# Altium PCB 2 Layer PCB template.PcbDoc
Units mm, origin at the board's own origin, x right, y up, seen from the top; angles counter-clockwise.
Board outline 100 x 100 mm, 2 copper layers (Top, Bottom), stack 1.67 mm thick; 2 components, 0 nets, 4 pads, 0 vias.
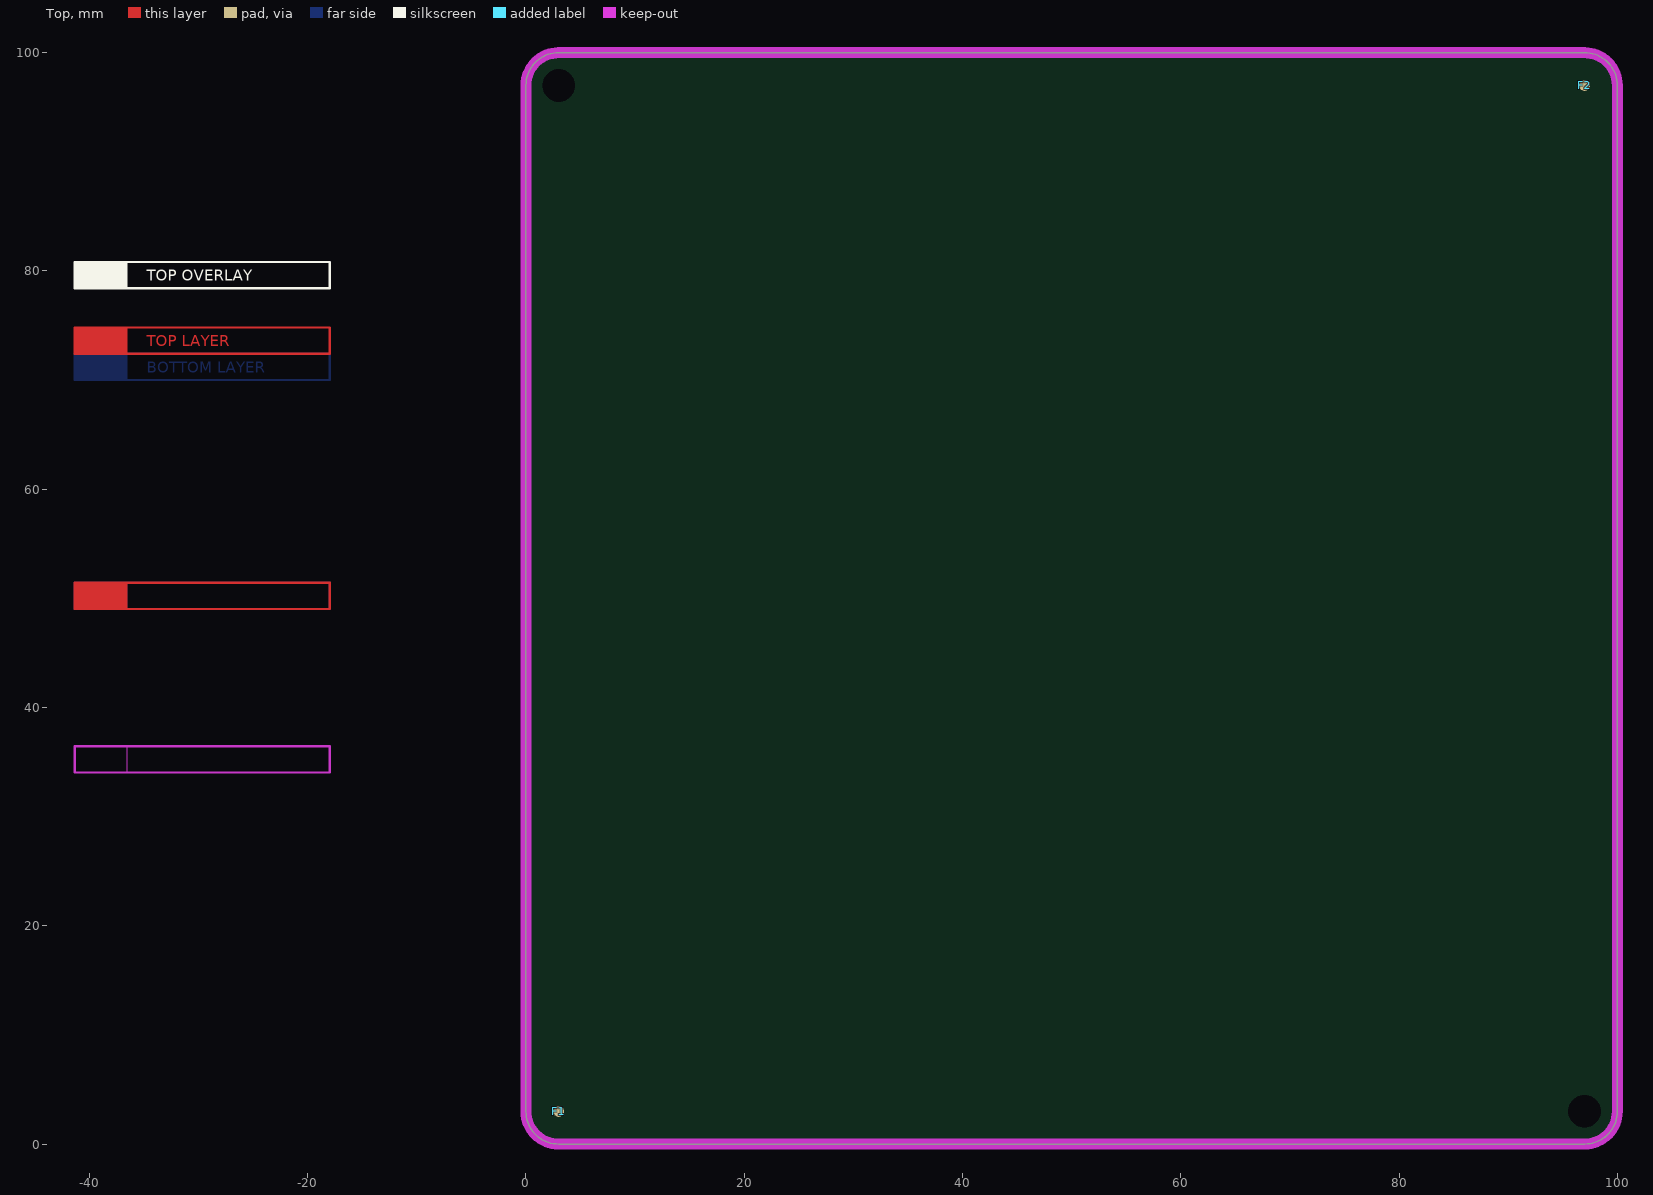
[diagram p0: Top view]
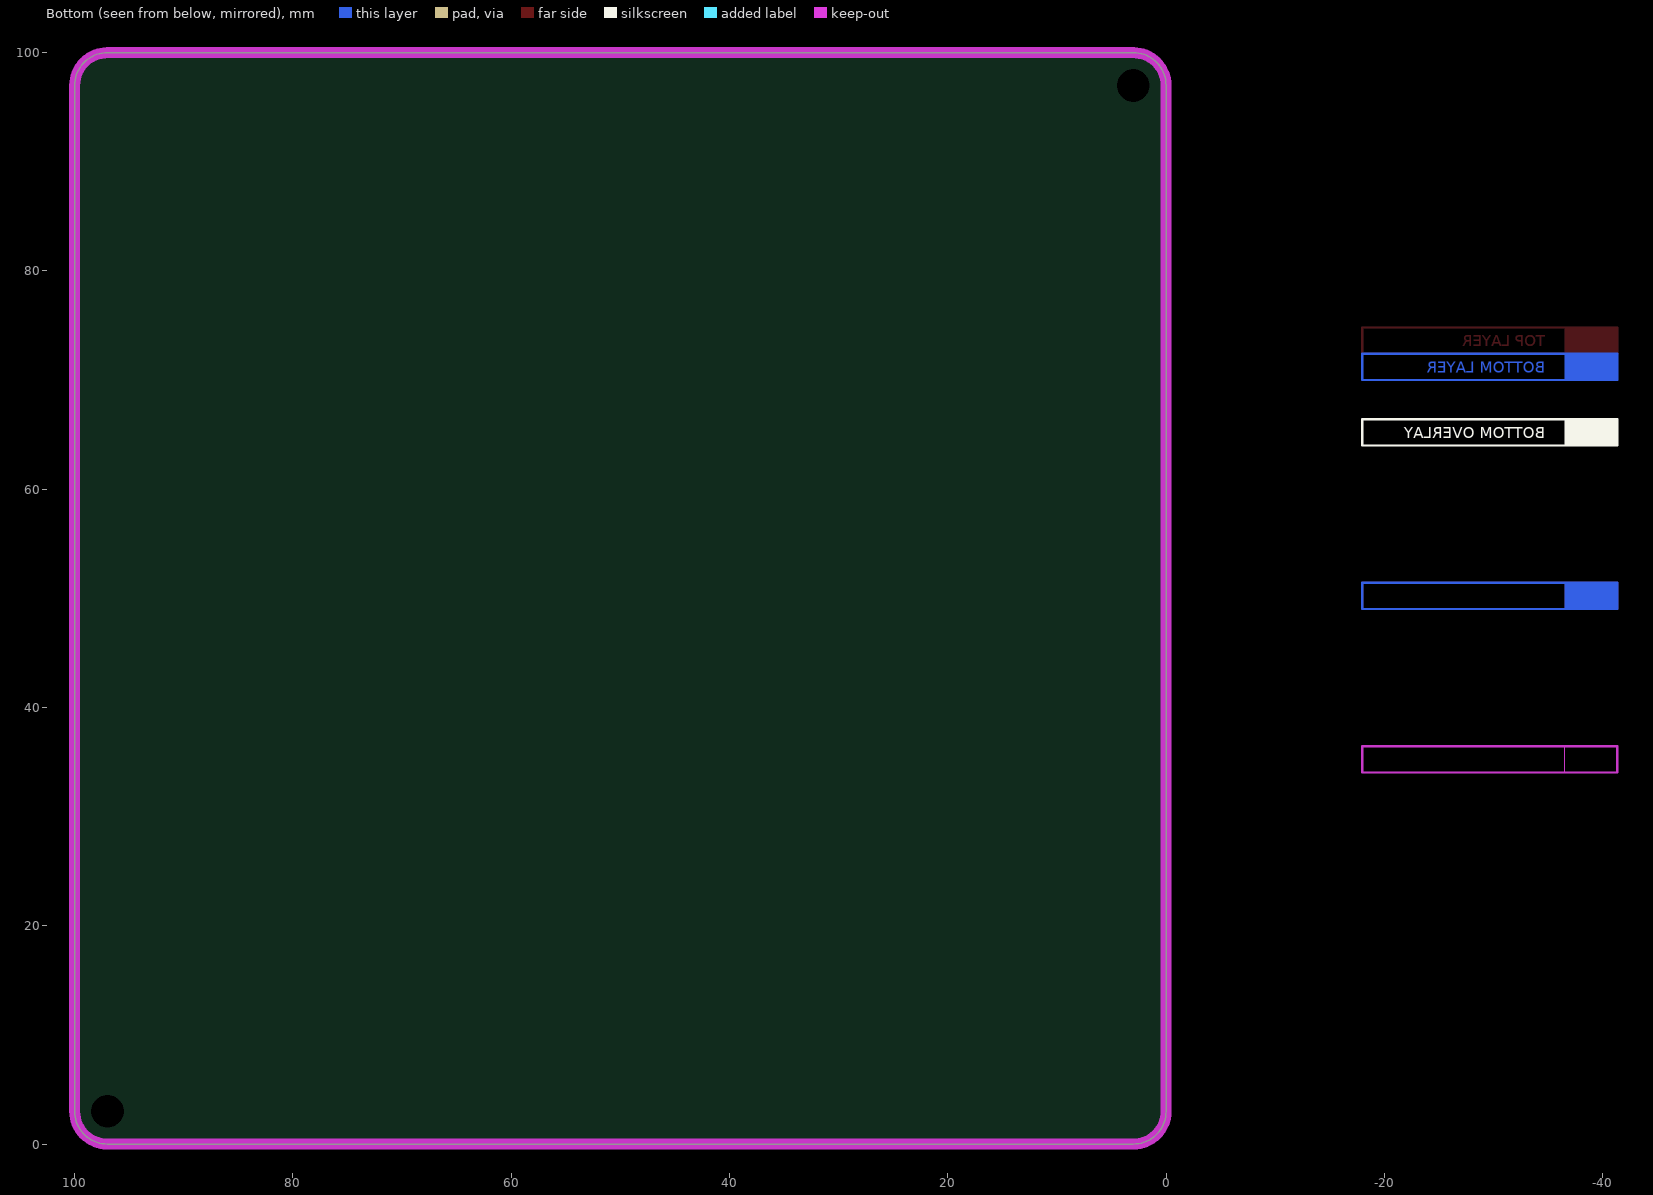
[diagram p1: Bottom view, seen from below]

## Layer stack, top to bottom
Top: signal copper 0.035
Dielectric: core 1.6, FR-4, Dk 4.8
Bottom: signal copper 0.035

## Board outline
0,3 0,97 cw(c3,97) 3,100 97,100 cw(c97,97) 100,97 100,3 cw(c97,3) 97,0 3,0 cw(c3,3)

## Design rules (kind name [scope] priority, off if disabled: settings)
AssemblyTestPointUsage [All] p1 off:
AssemblyTestpoint [All] p1 off: testpointundercomponent=TRUE minsize=1.016 maxsize=2.54 preferedsize=1.524 minholesize=0 maxholesize=1.016 preferedholesize=0.813 testpointgrid=0.025 usegrid=TRUE gridtolerance=0 allowsidetop=TRUE allowsidebottom=TRUE
Clearance ClearanceViaPad [IsVia vs IsPad] p1: gap=0.1
Clearance ClearanceGNDpolygons [InPolygonClass('GNDpolygons')] p2: gap=0.3
Clearance ClearanceTechnology [All] p3: gap=0.2
FabricationTestPointUsage [All] p1 off: valid=0 allowmultiple=FALSE
FabricationTestpoint [All] p1 off: side=3 testpointundercomponent=TRUE minsize=1.016 maxsize=2.54 preferedsize=1.524 minholesize=0 maxholesize=1.016 preferedholesize=0.813 testpointgrid=0.025 allowsidetop=TRUE allowsidebottom=TRUE usegrid=TRUE gridtolerance=0
HoleSize [All] p1: absolutevalues=TRUE maxlimit=6.3 minlimit=0.3 maxpercent=80.000 minpercent=20.000
HoleToHoleClearance [All] p1: gap=0.3 allowstackedmicrovias=TRUE
MinimumAnnularRing [All] p1: minimumring=0.2
MinimumSolderMaskSliver [All] p1: minsoldermaskwidth=0.1
PlaneClearance [All] p1: clearance=0.25
PolygonConnect PolygonConnectVia [IsVia] p1: connectstyle=Direct reliefconductorwidth=0.4 reliefentries=4 polygonreliefangle="90 Angle" airgapwidth=0.254
PolygonConnect PolygonConnectBigPads [(ObjectKind = 'Pad') And ((AsMM(PadXSize_AllLayers) > 2) Or (AsMM(PadYSize_AllLayers) > 2))] p2: connectstyle=Direct reliefconductorwidth=0.4 reliefentries=4 polygonreliefangle="90 Angle" airgapwidth=0.254
PolygonConnect PolygonConnectGeneral [All] p3: connectstyle=Relief reliefconductorwidth=0.3 reliefentries=4 polygonreliefangle="90 Angle" airgapwidth=0.2
RoutingVias [All] p1: holewidth=0.6 width=1.2 viastyle="Through Hole" minholewidth=0.3 minwidth=0.7 maxholewidth=0.9 maxwidth=1.4
SilkToSilkClearance [All] p1: silktosilkclearance=0.15
SilkToSolderMaskClearance SilkscreenOverComponentPads [IsPad] p1: minsilkscreentomaskgap=0.1 clearancetoexposedcopper=FALSE
SolderMaskExpansion [All] p1: expansion=0.1
Width WidthTechnology [All] p1: maxlimit=3 minlimit=0.16 preferedwidth=0.6
18 further rules are at their usual default settings.

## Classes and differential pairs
channel class "Column driver": "U_Column driver 1" "U_Column driver 2" "U_Column driver 3" "U_Column driver 4"
channel class "Row driver": "U_Row driver 1" "U_Row driver 2" "U_Row driver 3" "U_Row driver 4" "U_Row driver 5" "U_Row driver 6" "U_Row driver 7" "U_Row driver 8"

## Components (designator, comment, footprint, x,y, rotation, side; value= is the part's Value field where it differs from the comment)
F1 "Fiducial" FIDUCIAL 3,3 r90 top locked
F2 "Fiducial" FIDUCIAL 97,97 r90 top locked

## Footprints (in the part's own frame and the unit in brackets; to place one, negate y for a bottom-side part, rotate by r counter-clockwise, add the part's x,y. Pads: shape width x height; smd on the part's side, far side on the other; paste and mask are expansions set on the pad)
FIDUCIAL [mm] "Fiducial"
  round 1 smd paste-1 mask+0.5: ""(0,0)
  body extent -0.49,-0.5 0.5,0.5, height 0.5

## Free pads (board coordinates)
  round 1 hole 3: 0(3,97) 0(97,3)

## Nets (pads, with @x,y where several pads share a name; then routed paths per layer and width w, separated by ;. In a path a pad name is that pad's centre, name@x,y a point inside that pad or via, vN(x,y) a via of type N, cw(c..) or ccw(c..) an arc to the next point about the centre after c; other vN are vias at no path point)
pads on no net: F1. F2.
copper on no net: | length 103.1
  Top w0.2: -41.342,72.414 -41.342,74.827 -17.974,74.827 -17.974,72.414 -41.342,72.414
  Bottom w0.2: -41.342,70.001 -41.342,72.414 -17.974,72.414 -17.974,70.001 -41.342,70.001

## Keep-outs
Keep-Out Layer:
  rectangle: -41.342,34.035 -36.516,36.448
  lines w0.2: -41.342,34.035 -41.342,36.448 -17.974,36.448 -17.974,34.035 -41.342,34.035
  lines w1: 3,100 ccw(c3,97) 0,97 0,3 ccw(c3,3) 3,0 97,0 ccw(c97,3) 100,3 ; 3,100 3,100 ; 3,100 97,100 ; 97,100 cw(c97,97) 100,97 ; 97,100 97,100 ; 100,3 100,97 ; 100,3 100,3 ; 100,97 100,97
  text "ROUTING KEEPOUT LAYER" at -34.738,34.721 h0.89

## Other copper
Top:
  rectangle: -41.342,72.414 -36.516,74.827
  text "TOP LAYER" at -34.738,73.1 h1.02
Bottom:
  rectangle: -41.342,70.001 -36.516,72.414
  text "BOTTOM LAYER" at -34.738,70.687 h1.02
Multi-Layer:
  rectangle: -41.342,49.021 -36.516,51.434
  lines w0.2: -41.342,49.021 -41.342,51.434 -17.974,51.434 -17.974,49.021 -41.342,49.021
  text "MULTILAYER" at -34.738,49.707 h1.02

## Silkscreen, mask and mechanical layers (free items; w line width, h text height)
Top Overlay:
  rectangle: -41.342,78.409 -36.516,80.822
  lines w0.2: -41.342,78.409 -17.974,78.409 -17.974,80.822 -41.342,80.822 -41.342,78.409
  text "TOP OVERLAY" at -34.738,79.094 h1.02
Bottom Overlay:
  rectangle: -41.342,64.007 -36.516,66.42
  lines w0.2: -41.342,64.007 -17.974,64.007 -17.974,66.42 -41.342,66.42 -41.342,64.007
  text "BOTTOM OVERLAY" at -34.738,64.693 h1.02
Top Paste:
  rectangle: -41.342,81.406 -36.516,83.819
  lines w0.2: -41.342,81.406 -41.342,83.819 -17.974,83.819 -17.974,81.406 -41.342,81.406
  text "TOP PASTE" at -34.738,82.092 h1.02
Bottom Paste:
  rectangle: -41.342,61.01 -36.516,63.423
  lines w0.2: -41.342,61.01 -41.342,63.423 -17.974,63.423 -17.974,61.01 -41.342,61.01
  text "BOTTOM PASTE" at -34.738,61.695 h1.02
Top Solder:
  rectangle: -41.342,75.411 -36.516,77.824
  lines w0.2: -41.342,75.411 -17.974,75.411 -17.974,77.824 -41.342,77.824 -41.342,75.411
  text "TOP SOLDER MASK" at -34.738,76.097 h1.02
Bottom Solder:
  rectangle: -41.342,67.004 -36.516,69.417
  lines w0.2: -41.342,67.004 -41.342,69.417 -17.974,69.417 -17.974,67.004 -41.342,67.004
  text "BOTTOM SOLDER MASK" at -34.738,67.69 h1.02
Drill Guide:
  rectangle: -41.342,58.012 -36.516,60.425
  lines w0.2: -41.342,58.012 -17.974,58.012 -17.974,60.425 -41.342,60.425 -41.342,58.012
  text "DRILL GUIDE (SLOTS)" at -34.738,58.698 h1.02
Outline:
  rectangle: -41.342,52.018 -36.516,54.431
  lines w0.1: 0,3 ccw(c3,3) 3,0 97,0 ccw(c97,3) 100,3 100,97 ccw(c97,97) 97,100 3,100 ccw(c3,97) 0,97 0,3
  lines w0.2: -41.342,52.018 -17.974,52.018 -17.974,54.431 -41.342,54.431 -41.342,52.018
  lines w0.25: 119.824,-28.075 248.576,-28.075 ; 119.824,-23.725 248.576,-23.725 ; 118.3,-48 ccw(c119.7,-48) 119.7,-49.4 248.7,-49.4 ccw(c248.7,-48) 250.1,-48 250.1,-19 ccw(c248.7,-19) 248.7,-17.6 119.7,-17.6 ccw(c119.7,-19) 118.3,-19 118.3,-48
  lines w0.254: -43.882,117.702 69,117.702 69,112 ; -43.882,122.827 69,122.827 69,117.136 ; -39.056,86.105 -19.498,86.105 ; 33,112 33,117.702 ; 69,122.825 94.975,122.825 ; -43.882,31.825 -43.882,91.693 -15.18,91.693 -15.18,31.825 -43.882,31.825 ; -43.882,112 95,112 95,130.05 -43.882,130.05 -43.882,112
  text ".GlobalProjectName" at -32.125,124.975 h3
  text "Project:" at -42.406,124.816 h1.2
  text ".GlobalProjectTeam" at -34.65,119.3 h2.03
  text ".GlobalProjectLink" at 35.15,119.3 h2.03
  text "Team:" at -42.406,119.225 h1.2
  text "More info:" at 25.35,119.225 h1.2
  text ".GlobalProjectRevision" at 75,114 h7
  text ".Pcb_File_Name_No_Path" at -28,113.934 h2.03
  text "PCB file name:" at -42.406,113.907 h1.2
  text ".GlobalRevisionDate" at 48.119,113.507 h2.03
  text "Rev:" at 71,113.507 h1.2
  text "Revision date:" at 34.944,113.407 h1.2
  text "LAYER USAGE" at -39.056,86.816 h2.03
  text "Fusion service size limits" at 131,76.8 h5
  text "5cm X 5cm" at 134,71.802 h5
  text "5cm X 10cm" at 134,68.024 h5
  text "5cm X 15cm" at 134,64.246 h5
  text "5cm X 20cm" at 134,60.468 h5
  text "10cm X 10cm" at 134,56.69 h5
  text "10cm X 15cm" at 134,52.912 h5
  text "BOARD OUTLINE" at -34.738,52.704 h1.02
  text "10cm X 20cm" at 134,49.134 h5
  text "15cm X 15cm" at 134,45.356 h5
  text "15cm X 20cm" at 134,41.578 h5
  text "20cm X 20cm" at 134,37.8 h5
  text "Layer Stack Up Detail for: 2 Layer Seed Fusion template" at 119.824,-22.178 h2.05
  text "Layer" at 119.824,-25.35 h1
  text "Gerber" at 147.375,-25.35 h1
  text "Copper" at 161.317,-25.35 h1
  text "Dielectric" at 176.892,-25.35 h1
  text "Dielectric" at 193.166,-25.35 h1
  text "Dielectric" at 213.72,-25.35 h1
  text "Dielectric" at 229.994,-25.35 h1
  text "Name" at 119.824,-27.35 h1
  text "Document" at 147.375,-27.35 h1
  text "Thickness" at 161.317,-27.35 h1
  text "Height" at 176.892,-27.35 h1
  text "Material" at 193.166,-27.35 h1
  text "Constant" at 213.72,-27.35 h1
  text "Type" at 229.994,-27.35 h1
  text "Top Solder Mask" at 119.824,-31.222 h1.4
  text "(.GTS)" at 147.375,-31.222 h1.4
  text "0.0102mm" at 176.892,-31.222 h1.4
  text "Solder Resist" at 193.166,-31.222 h1.4
  text "3.50" at 213.72,-31.222 h1.4
  text "Top" at 119.824,-35.252 h1.4
  text "(.GTL)" at 147.375,-35.252 h1.4
  text "0.035mm" at 161.317,-35.252 h1.4
  text "1.6mm" at 176.892,-37.267 h1.4
  text "FR-4" at 193.166,-37.267 h1.4
  text "4.80" at 213.72,-37.267 h1.4
  text "Core" at 229.994,-37.267 h1.4
  text "Bottom" at 119.824,-39.282 h1.4
  text "(.GBL)" at 147.375,-39.282 h1.4
  text "0.035mm" at 161.317,-39.282 h1.4
  text "Bottom Solder Mask" at 119.824,-43.312 h1.4
  text "(.GBS)" at 147.375,-43.312 h1.4
  text "0.0102mm" at 176.892,-43.312 h1.4
  text "Solder Resist" at 193.166,-43.312 h1.4
  text "3.50" at 213.72,-43.312 h1.4
Dimensions:
  rectangle: -41.342,37.032 -36.516,39.445
  lines w0.2: -41.146,-10.834 -23.061,-10.834 ; -41.07,-2.782 -22.985,-2.782 ; -41.07,16.369 -22.985,16.369 ; -41.045,8.673 -22.96,8.673 ; -40.918,19.798 -22.833,19.798 ; -41.342,37.032 -17.974,37.032 -17.974,39.445 -41.342,39.445 -41.342,37.032
  lines w0.254: -42.064,-17.8 -42.064,23.583 -17.908,23.583 -17.908,-17.8 -42.064,-17.8
  text "DIMENSIONS" at -34.738,37.718 h1.02
  text "BUILD STATISTICS" at -40.816,20.586 h1.52
  text "GENERAL" at -41.019,16.877 h1.02
  text ".Net_Count" at -31.342,14.769 h1.02
  text "NETS" at -40.943,14.718 h0.89
  text ".Component_Count" at -31.342,12.686 h1.02
  text "COMPONENTS" at -40.918,12.661 h0.89
  text "PRIMITIVES" at -40.994,9.181 h1.02
  text ".Fill_Count" at -31.342,7.048 h1.02
  text "FILLS" at -40.918,7.022 h0.89
  text ".Track_Count" at -31.342,4.99 h1.02
  text "TRACKS" at -40.918,4.939 h0.89
  text ".String_Count" at -31.342,2.907 h1.02
  text "STRINGS" at -40.918,2.857 h0.89
  text ".Arc_Count" at -31.342,0.799 h1.02
  text "ARC'S" at -40.918,0.748 h0.89
  text "LANDS" at -41.019,-2.274 h1.02
  text ".Pad_Count" at -31.342,-4.408 h1.02
  text ".Pad_Count" at -31.342,-4.408 h1.02
  text "PADS" at -40.918,-4.459 h0.89
  text ".Via_Count" at -31.342,-6.491 h1.02
  text "VIA'S" at -40.892,-6.516 h0.89
  text "PRINT SCALE" at -41.095,-10.326 h1.02
  text ".Print_Scale" at -31.393,-12.485 h1.02
  text "SCALE" at -40.968,-12.51 h0.89
  text ".Print_Date" at -31.393,-14.542 h1.02
  text "PRINT DATE" at -40.943,-14.568 h0.89
  text ".Print_Time" at -31.367,-16.6 h1.02
  text "PRINT TIME" at -40.918,-16.625 h0.89
Assembly Top:
  rectangle: -41.342,46.024 -36.516,48.437
  lines w0.2: -41.342,46.024 -41.342,48.437 -17.974,48.437 -17.974,46.024 -41.342,46.024
  text "TOP ASSEMBLY" at -34.738,46.709 h1.02
Assembly Bot:
  rectangle: -41.342,43.026 -36.516,45.439
  lines w0.2: -41.342,43.026 -41.342,45.439 -17.974,45.439 -17.974,43.026 -41.342,43.026
  text "BOTTOM ASSEMBLY" at -34.738,43.712 h1.02
Drill Drawing:
  rectangle: -41.342,55.015 -36.516,57.428
  lines w0.025: -0.319,-43.866 0.316,-43.548 0.951,-43.866 0.633,-43.231 0.951,-42.596 0.316,-42.913 -0.319,-42.596 -0.002,-43.231 -0.319,-43.866
  lines w0.2: -41.342,55.015 -41.342,57.428 -17.974,57.428 -17.974,55.015 -41.342,55.015
  lines w0.381: -2.05,-45.009 96.476,-45.009 ; -2.05,-41.199 96.476,-41.199 ; 11.943,-48.819 11.943,-37.389 ; 29.667,-48.819 29.667,-37.389 ; 63.846,-48.819 63.846,-37.389 ; 76.695,-48.819 76.695,-37.389 ; -2.05,-48.819 96.476,-48.819 96.476,-37.389 -2.05,-37.389 -2.05,-48.819
  text "DRILL DRAWING" at -34.738,55.701 h1.02
  text "Symbol" at 0.236,-40.056 h1.83
  text "Hit Count" at 13.086,-40.056 h1.83
  text "Finished Hole Size" at 30.81,-40.056 h1.83
  text "Plated" at 64.989,-40.056 h1.83
  text "Hole Type" at 77.838,-40.056 h1.83
  text "2" at 13.086,-43.866 h1.52
  text "3.0mm" at 30.81,-43.866 h1.52
  text "PTH" at 64.989,-43.866 h1.52
  text "Round" at 77.838,-43.866 h1.52
  text "2 Total" at 13.086,-47.676 h1.52

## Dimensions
97,0 to 97,100 on Dimensions
0,3 to 100,3 on Dimensions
